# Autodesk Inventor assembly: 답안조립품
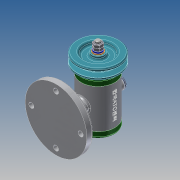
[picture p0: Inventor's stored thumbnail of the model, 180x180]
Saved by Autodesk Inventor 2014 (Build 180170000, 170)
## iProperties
Created: 2018-12
Part Number: 답안조립품
Document SubType Name: Assembly
Designer: kb542-14
Author: kb542-14
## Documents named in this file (15)
- C:\Users\kb542-14\Desktop\481207V1009\답안조립품.iam
- C:\Users\kb542-14\Desktop\481207V1009\V벨트풀리.ipt
- C:\Users\kb542-14\Desktop\481207V1009\고무캡.ipt
- C:\Users\kb542-14\Desktop\481207V1009\너트 M8.ipt
- 너트 M8.ipt
- C:\Users\kb542-14\Desktop\481207V1009\뒤커버.ipt
- C:\Users\kb542-14\Desktop\481207V1009\베어링 15 x 32 x 9.ipt
- C:\Users\kb542-14\Desktop\481207V1009\본체.ipt
- C:\Users\kb542-14\Desktop\481207V1009\볼트 M4 x 12.ipt
- C:\Users\kb542-14\Desktop\481207V1009\스프링와셔 8.ipt
- C:\Users\kb542-14\Desktop\481207V1009\앞커버.ipt
- C:\Users\kb542-14\Desktop\481207V1009\오일 실 15 25 7.ipt
- C:\Users\kb542-14\Desktop\481207V1009\와셔 8x17.ipt
- C:\Users\kb542-14\Desktop\481207V1009\축.ipt
- C:\Users\kb542-14\Desktop\481207V1009\키 3 x 3 x 12.ipt
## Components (2 placed, 2 different names)
1. V벨트풀리:1 — 각도:2
2. 고무캡:1
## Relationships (1: Angle 1)
- 각도:2 [Angle]: V벨트풀리:1
